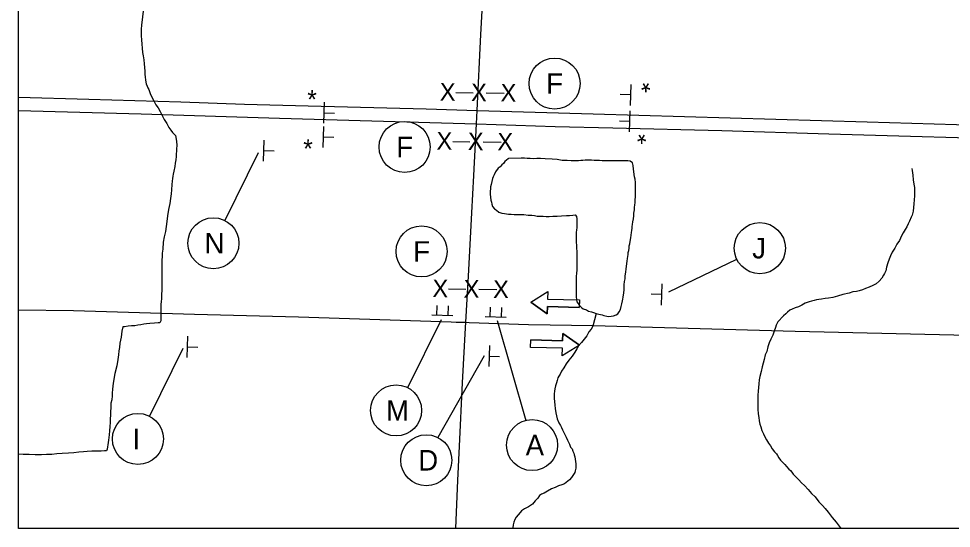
# Model space of a CAD drawing. Extents: x 1633.3 to 1707.6, y 1081.5 to 1106.
# Drawn here: x 1633.31 to 1640.38, y 1086.42 to 1090.29 of the extents above; entities that cross this region are included whole.
import ezdxf

# ---------------------------------------------------------------- set-up
doc = ezdxf.new("R2010")
doc.units = 0
for name, color, linetype in [('GM_X_County_Road', 7, 'Continuous'), ('GM_X_Minor_Lake', 7, 'Continuous'), ('GM_X_Minor_River', 7, 'Continuous'), ('GM_X_State_Route', 7, 'Continuous'), ('GM_X_Township_Road', 7, 'Continuous'), ('SH_Data', 7, 'Continuous'), ('SH_Text', 7, 'Continuous'), ('SN_P_Signs', 7, 'Continuous'), ('SN_X_Public', 7, 'Continuous')]:
    doc.layers.add(name, color=color, linetype=linetype)

msp = doc.modelspace()

# ---------------------------------------------------------------- linework, layer by layer
at = {"layer": 'GM_X_County_Road'}
for points in [[(1636.7895, 1089.5915), (1636.8181, 1090.1691), (1636.886, 1091.3924), (1636.9148, 1091.8728), (1636.9362, 1092.288), (1636.9703, 1092.8778), (1636.974, 1092.925), (1636.9808, 1092.9969), (1636.984, 1093.031)], [(1636.7846, 1089.489), (1636.7895, 1089.5915)], [(1636.7029, 1087.9843), (1636.723, 1088.3341), (1636.7482, 1088.8147), (1636.7628, 1089.0988), (1636.7846, 1089.489)], [(1633.3121, 1088.0796), (1633.7283, 1088.0729), (1634.6468, 1088.0465), (1635.434, 1088.0244), (1636.593, 1087.987), (1636.6307, 1087.986), (1636.7029, 1087.9843)], [(1636.7029, 1087.9843), (1636.7291, 1087.9834), (1637.1782, 1087.9683), (1637.6688, 1087.9589), (1639.2, 1087.9178), (1640.4033, 1087.8897), (1641.5407, 1087.8579), (1642.8312, 1087.8177), (1643.7062, 1087.7937), (1643.8593, 1087.7897)]]:
    msp.add_lwpolyline(points, dxfattribs=at)
at = {"layer": 'GM_X_Minor_Lake'}
for points in [[(1637.0279, 1089.2269), (1637.0241, 1089.2247), (1637, 1089.2034), (1636.9892, 1089.19), (1636.9758, 1089.1794), (1636.9624, 1089.1634), (1636.949, 1089.1527), (1636.9275, 1089.126), (1636.9168, 1089.102), (1636.9114, 1089.0886), (1636.906, 1089.0753), (1636.8952, 1089.0298), (1636.8898, 1089.0111), (1636.8898, 1088.9977), (1636.8871, 1088.979), (1636.887, 1088.9576), (1636.8896, 1088.9335), (1636.8923, 1088.9121), (1636.8976, 1088.896), (1636.9002, 1088.88), (1636.9055, 1088.8639), (1636.9216, 1088.8451), (1636.9349, 1088.8344), (1636.9536, 1088.8209), (1636.975, 1088.8128), (1636.9964, 1088.8101), (1637.0124, 1088.8074), (1637.0258, 1088.8047), (1637.0472, 1088.8046), (1637.0686, 1088.8018), (1637.0927, 1088.8018), (1637.1168, 1088.8017), (1637.1435, 1088.8016), (1637.1756, 1088.7962), (1637.2024, 1088.7961), (1637.2238, 1088.7933), (1637.2452, 1088.7906), (1637.2693, 1088.7905), (1637.2907, 1088.7904), (1637.3121, 1088.7877), (1637.3362, 1088.7876), (1637.3629, 1088.7902), (1637.395, 1088.7901), (1637.4298, 1088.7927), (1637.4673, 1088.7952), (1637.4887, 1088.7952), (1637.5154, 1088.7977), (1637.5315, 1088.8004), (1637.5422, 1088.787), (1637.5448, 1088.7682), (1637.5448, 1088.7522), (1637.5447, 1088.7308), (1637.5447, 1088.7174), (1637.5447, 1088.7013), (1637.542, 1088.6853), (1637.5392, 1088.6666), (1637.5392, 1088.6479), (1637.5392, 1088.6345), (1637.5391, 1088.6184), (1637.5391, 1088.6024), (1637.5391, 1088.589), (1637.5417, 1088.5702), (1637.5416, 1088.5462), (1637.5443, 1088.5221), (1637.5442, 1088.498), (1637.5442, 1088.4793), (1637.5441, 1088.4632), (1637.5441, 1088.4418), (1637.544, 1088.4231), (1637.544, 1088.4044), (1637.5439, 1088.3803), (1637.5412, 1088.3562), (1637.5411, 1088.3321), (1637.5411, 1088.3081), (1637.541, 1088.2893), (1637.541, 1088.2706), (1637.541, 1088.2492), (1637.5409, 1088.2331), (1637.5409, 1088.2171), (1637.5408, 1088.1984), (1637.5408, 1088.1796), (1637.5434, 1088.1555), (1637.546, 1088.1395), (1637.554, 1088.1261), (1637.5647, 1088.1127), (1637.5807, 1088.0966), (1637.5941, 1088.0858), (1637.6182, 1088.0777), (1637.6342, 1088.0696), (1637.6556, 1088.0642), (1637.6716, 1088.0588), (1637.6903, 1088.0507), (1637.7117, 1088.0453), (1637.7358, 1088.0399), (1637.7492, 1088.0345), (1637.7732, 1088.0317), (1637.7866, 1088.029), (1637.8054, 1088.0316), (1637.8241, 1088.0343), (1637.8428, 1088.0396)], [(1637.8428, 1088.0396), (1637.8562, 1088.0475), (1637.867, 1088.0635), (1637.875, 1088.0823), (1637.8804, 1088.1036), (1637.8858, 1088.125), (1637.8912, 1088.1464), (1637.894, 1088.1598), (1637.8967, 1088.1758), (1637.9021, 1088.2079), (1637.9048, 1088.2293), (1637.9049, 1088.248), (1637.9049, 1088.2694), (1637.9076, 1088.2935), (1637.9104, 1088.3149), (1637.9104, 1088.3336), (1637.9131, 1088.3523), (1637.9158, 1088.3657), (1637.9186, 1088.3898), (1637.9267, 1088.4486), (1637.9294, 1088.4673), (1637.9322, 1088.4834), (1637.9349, 1088.4994), (1637.9349, 1088.5128), (1637.9403, 1088.5289), (1637.943, 1088.5476), (1637.943, 1088.5636), (1637.9458, 1088.5797), (1637.9485, 1088.5984), (1637.9539, 1088.6251), (1637.9566, 1088.6465), (1637.9593, 1088.6652), (1637.962, 1088.6813), (1637.9648, 1088.6973), (1637.9648, 1088.7107), (1637.9675, 1088.7267), (1637.9702, 1088.7455), (1637.9756, 1088.7695), (1637.9784, 1088.7909), (1637.9784, 1088.8123), (1637.9811, 1088.8364), (1637.9812, 1088.8578), (1637.9839, 1088.8738), (1637.9866, 1088.8926), (1637.9866, 1088.914), (1637.9894, 1088.9354), (1637.9894, 1088.9568), (1637.9895, 1088.9755), (1637.9895, 1088.9942), (1637.9896, 1089.0129), (1637.9896, 1089.029), (1637.9896, 1089.0451), (1637.987, 1089.0691), (1637.9817, 1089.0879), (1637.9791, 1089.1066), (1637.9764, 1089.128), (1637.9738, 1089.1468), (1637.9712, 1089.1735), (1637.9659, 1089.1949), (1637.9499, 1089.2057), (1637.9311, 1089.2084), (1637.9097, 1089.2085), (1637.8964, 1089.2085), (1637.8803, 1089.2086), (1637.8562, 1089.2087), (1637.8402, 1089.2087), (1637.8268, 1089.2088), (1637.8107, 1089.2088), (1637.7974, 1089.2089), (1637.784, 1089.2089), (1637.7679, 1089.209), (1637.7519, 1089.209), (1637.7358, 1089.2091), (1637.7171, 1089.2118), (1637.6984, 1089.2119), (1637.6769, 1089.2119), (1637.6556, 1089.2147), (1637.6261, 1089.2148), (1637.6074, 1089.2148), (1637.5913, 1089.2122), (1637.5753, 1089.2123), (1637.5565, 1089.2096), (1637.5325, 1089.2097), (1637.503, 1089.2098), (1637.4709, 1089.2126), (1637.4335, 1089.2127), (1637.396, 1089.2182), (1637.3586, 1089.221), (1637.305, 1089.2238), (1637.2703, 1089.2266), (1637.2408, 1089.2267), (1637.2141, 1089.2241), (1637.19, 1089.2269), (1637.1686, 1089.2269), (1637.1472, 1089.2297), (1637.1231, 1089.2297), (1637.0279, 1089.2269)]]:
    msp.add_lwpolyline(points, dxfattribs=at)
at = {"layer": 'GM_X_Minor_River'}
for points in [[(1634.26, 1090.3652), (1634.2436, 1090.2395), (1634.2409, 1090.2074), (1634.2408, 1090.1833), (1634.2408, 1090.1566), (1634.2434, 1090.1272), (1634.246, 1090.0951), (1634.2486, 1090.0629), (1634.2512, 1090.0308), (1634.2565, 1090.0067), (1634.2618, 1089.9746), (1634.2644, 1089.9452), (1634.267, 1089.9184), (1634.2696, 1089.889), (1634.2695, 1089.8676), (1634.2722, 1089.8435), (1634.2748, 1089.8247), (1634.2774, 1089.806), (1634.2801, 1089.7926), (1634.2854, 1089.7765), (1634.2907, 1089.7632), (1634.2987, 1089.7497), (1634.3094, 1089.7203), (1634.3227, 1089.6935), (1634.336, 1089.664), (1634.352, 1089.6345), (1634.3706, 1089.6104), (1634.384, 1089.5836), (1634.3999, 1089.5541), (1634.4159, 1089.522), (1634.4346, 1089.4925), (1634.4506, 1089.463), (1634.4666, 1089.4415), (1634.4799, 1089.4254), (1634.5013, 1089.4013), (1634.5092, 1089.3585), (1634.5118, 1089.3263), (1634.5091, 1089.2996)], [(1634.5091, 1089.2996), (1634.509, 1089.2809), (1634.5063, 1089.2648), (1634.5062, 1089.2434), (1634.5035, 1089.2167), (1634.4981, 1089.1926), (1634.4954, 1089.1659), (1634.4899, 1089.1311), (1634.4845, 1089.1071), (1634.4818, 1089.0937), (1634.4791, 1089.075), (1634.4764, 1089.0562), (1634.4736, 1089.0295), (1634.4709, 1088.9894), (1634.4682, 1088.96), (1634.4627, 1088.9225), (1634.4573, 1088.8851), (1634.4491, 1088.8396), (1634.441, 1088.7915), (1634.4356, 1088.7487), (1634.4301, 1088.7113), (1634.4247, 1088.6738), (1634.4166, 1088.6337), (1634.4084, 1088.5909), (1634.4056, 1088.5401), (1634.4002, 1088.508), (1634.4002, 1088.4813), (1634.3974, 1088.4572), (1634.3974, 1088.4304), (1634.3973, 1088.409), (1634.3973, 1088.3876), (1634.3972, 1088.3635), (1634.3971, 1088.3315), (1634.3971, 1088.2993), (1634.397, 1088.2646), (1634.3969, 1088.2325), (1634.3941, 1088.1897), (1634.3941, 1088.1629), (1634.394, 1088.1415), (1634.3913, 1088.1201), (1634.3913, 1088.1014), (1634.3912, 1088.0746), (1634.3911, 1088.0532), (1634.3911, 1088.0318), (1634.3911, 1088.0131), (1634.391, 1087.9944), (1634.383, 1087.981), (1634.3696, 1087.9811), (1634.3428, 1087.9785), (1634.308, 1087.9759), (1634.2813, 1087.9733), (1634.2625, 1087.9707), (1634.2384, 1087.9654), (1634.217, 1087.9628), (1634.1929, 1087.9575), (1634.1688, 1087.9576), (1634.1421, 1087.955), (1634.1153, 1087.9498), (1634.1019, 1087.9498), (1634.0938, 1087.9177), (1634.0884, 1087.8723), (1634.0802, 1087.8268), (1634.0775, 1087.792), (1634.0721, 1087.768), (1634.0693, 1087.7385), (1634.0639, 1087.7011), (1634.0558, 1087.653), (1634.0423, 1087.5968), (1634.0287, 1087.522), (1634.0232, 1087.4765), (1634.0205, 1087.4471), (1634.0205, 1087.4257), (1634.0177, 1087.3962), (1634.0123, 1087.3695), (1634.0122, 1087.3374), (1634.0095, 1087.3053), (1634.0094, 1087.2785), (1634.0067, 1087.2518), (1634.0066, 1087.2251), (1634.0039, 1087.1929), (1634.0011, 1087.1609), (1633.9984, 1087.1314), (1633.9957, 1087.11), (1633.9929, 1087.0886), (1633.9902, 1087.0726), (1633.9821, 1087.0218), (1633.9794, 1087.0084), (1633.9633, 1087.0085), (1633.9366, 1087.0059), (1633.9044, 1087.006), (1633.867, 1087.0061), (1633.8322, 1087.0035), (1633.8028, 1087.001), (1633.768, 1086.9984), (1633.7305, 1086.9932), (1633.6903, 1086.9906), (1633.6422, 1086.9881), (1633.602, 1086.9855), (1633.5646, 1086.9803), (1633.5244, 1086.9804), (1633.4843, 1086.9779)], [(1640.085, 1089.1507), (1640.0876, 1089.1347), (1640.0929, 1089.0999), (1640.0955, 1089.0651), (1640.1008, 1089.033), (1640.1061, 1089.0062), (1640.106, 1088.9768), (1640.1059, 1088.9447), (1640.1032, 1088.9126), (1640.1004, 1088.8831), (1640.0977, 1088.8564), (1640.0949, 1088.827), (1640.0868, 1088.7976), (1640.0815, 1088.7815), (1640.068, 1088.7521), (1640.0573, 1088.7308), (1640.0465, 1088.7094), (1640.0358, 1088.688), (1640.0196, 1088.664), (1640.0062, 1088.64), (1639.9928, 1088.6052), (1639.9713, 1088.5759), (1639.9552, 1088.5465), (1639.9364, 1088.5171), (1639.9229, 1088.4877), (1639.9122, 1088.4637), (1639.9041, 1088.4343), (1639.8933, 1088.4022), (1639.8879, 1088.3755), (1639.8771, 1088.3541), (1639.8717, 1088.3408), (1639.8583, 1088.3194), (1639.8369, 1088.2954), (1639.8154, 1088.2767), (1639.7886, 1088.2634), (1639.7618, 1088.2501), (1639.735, 1088.2395), (1639.711, 1088.2316), (1639.6868, 1088.2236), (1639.6654, 1088.2183), (1639.6387, 1088.2158), (1639.6092, 1088.2051), (1639.561, 1088.1946), (1639.5209, 1088.1813), (1639.486, 1088.1734), (1639.4539, 1088.1682), (1639.4272, 1088.1656), (1639.4004, 1088.1603), (1639.379, 1088.1577), (1639.3629, 1088.1551), (1639.3442, 1088.1498), (1639.3254, 1088.1445), (1639.3067, 1088.1392), (1639.2772, 1088.1286), (1639.2504, 1088.1153), (1639.2263, 1088.102), (1639.1996, 1088.0941), (1639.1781, 1088.0835), (1639.1594, 1088.0755), (1639.1433, 1088.0622), (1639.1299, 1088.0488), (1639.1111, 1088.0328), (1639.0682, 1087.9875), (1639.0575, 1087.9634), (1639.0521, 1087.9447), (1639.0413, 1087.918), (1639.0305, 1087.8859), (1639.0171, 1087.8566), (1639.0036, 1087.8272), (1638.9928, 1087.7978), (1638.9847, 1087.763), (1638.974, 1087.7363), (1638.9659, 1087.7015), (1638.9497, 1087.6454), (1638.9416, 1087.6107), (1638.9335, 1087.5732), (1638.928, 1087.5465), (1638.9253, 1087.5171), (1638.9226, 1087.4903), (1638.9198, 1087.4609), (1638.9171, 1087.4315), (1638.917, 1087.394), (1638.9169, 1087.3592), (1638.9168, 1087.3245), (1638.9194, 1087.2897), (1638.9247, 1087.2629), (1638.9274, 1087.2361), (1638.9326, 1087.212), (1638.9406, 1087.1906), (1638.9486, 1087.1638), (1638.9592, 1087.137), (1638.9699, 1087.1156), (1638.9832, 1087.0915), (1638.9992, 1087.0673), (1639.0125, 1087.0459), (1639.0259, 1087.0245), (1639.0445, 1087.0003), (1639.0579, 1086.9869), (1639.0659, 1086.9735), (1639.0765, 1086.9547), (1639.0899, 1086.9386)], [(1637.6903, 1088.0507), (1637.666, 1087.9545), (1637.6526, 1087.9331), (1637.6365, 1087.9118), (1637.6204, 1087.8824), (1637.6016, 1087.8557), (1637.5801, 1087.8317), (1637.5587, 1087.805), (1637.5452, 1087.7837), (1637.5291, 1087.7569), (1637.5103, 1087.7276), (1637.4835, 1087.6956), (1637.4647, 1087.6689), (1637.4459, 1087.6395), (1637.4298, 1087.6128), (1637.419, 1087.5914), (1637.4083, 1087.5754), (1637.4002, 1087.5621), (1637.3948, 1087.5433), (1637.3895, 1087.5246), (1637.384, 1087.5032), (1637.3786, 1087.4792), (1637.3759, 1087.4605), (1637.3732, 1087.4417), (1637.3732, 1087.4257), (1637.3731, 1087.407), (1637.3758, 1087.3829), (1637.3784, 1087.3561), (1637.381, 1087.3293), (1637.3863, 1087.2972), (1637.3969, 1087.2517), (1637.4075, 1087.2223), (1637.4208, 1087.2008), (1637.4288, 1087.1847), (1637.4368, 1087.1686), (1637.4448, 1087.1526), (1637.4528, 1087.1338), (1637.4634, 1087.1124), (1637.4741, 1087.0909), (1637.4821, 1087.0749), (1637.4901, 1087.0588), (1637.498, 1087.0373), (1637.5087, 1087.0239), (1637.514, 1087.0052), (1637.522, 1086.9918), (1637.5247, 1086.9784), (1637.53, 1086.9623), (1637.5379, 1086.9115), (1637.5379, 1086.8954), (1637.5378, 1086.8767), (1637.5324, 1086.858), (1637.5297, 1086.8446), (1637.5136, 1086.8206), (1637.5055, 1086.8072), (1637.4894, 1086.7886), (1637.476, 1086.7779), (1637.4519, 1086.7593), (1637.4305, 1086.7513), (1637.4064, 1086.7433), (1637.3796, 1086.7301), (1637.3528, 1086.7194), (1637.3234, 1086.7035), (1637.2966, 1086.6875), (1637.2778, 1086.6795), (1637.2617, 1086.6689), (1637.2483, 1086.6502), (1637.2295, 1086.6289), (1637.2081, 1086.6049), (1637.1786, 1086.5835), (1637.1625, 1086.5756), (1637.1491, 1086.5676), (1637.125, 1086.5543), (1637.1143, 1086.5409), (1637.1008, 1086.5223), (1637.0848, 1086.5063), (1637.074, 1086.4876), (1637.0659, 1086.4689), (1637.0632, 1086.4475), (1637.0605, 1086.4234), (1637.0605, 1086.4207)], [(1633.4843, 1086.9779), (1633.4361, 1086.9781), (1633.3906, 1086.9809), (1633.3452, 1086.981), (1633.3121, 1086.9831)], [(1639.0899, 1086.9386), (1639.1032, 1086.9252), (1639.1219, 1086.9064), (1639.1353, 1086.8903), (1639.1513, 1086.8689), (1639.1646, 1086.8608), (1639.1753, 1086.8474), (1639.186, 1086.8313), (1639.2287, 1086.7884), (1639.2474, 1086.7669), (1639.2714, 1086.7454), (1639.2981, 1086.7159), (1639.3248, 1086.6864), (1639.3515, 1086.6596), (1639.3808, 1086.622), (1639.4075, 1086.5952), (1639.4289, 1086.571), (1639.4502, 1086.5442), (1639.4662, 1086.5227), (1639.4822, 1086.504), (1639.4956, 1086.4852), (1639.5116, 1086.4664), (1639.5276, 1086.4476), (1639.5409, 1086.4262), (1639.5457, 1086.4207)]]:
    msp.add_lwpolyline(points, dxfattribs=at)
at = {"layer": 'GM_X_State_Route'}
for points in [[(1633.3121, 1089.6917), (1633.8444, 1089.6764), (1634.5421, 1089.656), (1635.0244, 1089.6397), (1635.5067, 1089.6277), (1636.4013, 1089.603), (1636.7895, 1089.5915), (1637.6692, 1089.5652), (1639.746, 1089.5046), (1640.4237, 1089.486), (1640.9483, 1089.4695), (1641.5823, 1089.4514), (1642.6316, 1089.4208), (1643.4405, 1089.3971), (1643.9071, 1089.384), (1643.9651, 1089.3826), (1644.8177, 1089.3571), (1645.2987, 1089.3441), (1645.9544, 1089.3239), (1646.3915, 1089.3102), (1647.5918, 1089.2715), (1647.7355, 1089.2693), (1648.0121, 1089.264)], [(1633.3121, 1089.5922), (1634.2415, 1089.565), (1635.2906, 1089.5338), (1635.99, 1089.5137), (1636.7846, 1089.489), (1637.3802, 1089.4708), (1637.8182, 1089.4595), (1638.6457, 1089.4389), (1639.4549, 1089.4149), (1641.0515, 1089.3682), (1641.6858, 1089.3496), (1642.145, 1089.338), (1643.2823, 1089.3034), (1643.9044, 1089.2854), (1644.5726, 1089.2656), (1645.9723, 1089.2243), (1647.0002, 1089.1934), (1647.8935, 1089.1689), (1648.0121, 1089.1646)]]:
    msp.add_lwpolyline(points, dxfattribs=at)
at = {"layer": 'GM_X_Township_Road'}
msp.add_lwpolyline([(1636.628, 1086.4207), (1636.6329, 1086.5425), (1636.6436, 1086.7828), (1636.655, 1087.0451), (1636.6786, 1087.5259), (1636.7003, 1087.941), (1636.7029, 1087.9843)], dxfattribs=at)
at = {"layer": 'SH_Data'}
msp.add_lwpolyline([(1633.3121, 1106.0207), (1648.0121, 1106.0207), (1648.0121, 1086.4207), (1633.3121, 1086.4207)], close=True, dxfattribs=at)
at = {"layer": 'SH_Text'}
for p, q in [((1635.1295, 1089.2708), (1634.8764, 1088.7569)), ((1638.2414, 1088.2151), (1638.7572, 1088.4644)), ((1637.1949, 1088.1366), (1637.3248, 1088.2177)), ((1637.3248, 1088.2177), (1637.3231, 1088.1608)), ((1637.1949, 1088.1366), (1637.3199, 1088.0482)), ((1637.3199, 1088.0482), (1637.3215, 1088.1028)), ((1637.3215, 1088.1028), (1637.5634, 1088.0959)), ((1637.3231, 1088.1608), (1637.5651, 1088.1539)), ((1637.5651, 1088.1539), (1637.5634, 1088.0959)), ((1636.5152, 1088.0018), (1636.262, 1087.4879)), ((1636.9401, 1087.9983), (1637.1579, 1087.2402)), ((1637.4389, 1087.8992), (1637.4373, 1087.8447)), ((1637.5639, 1087.8108), (1637.4389, 1087.8992)), ((1637.1937, 1087.7936), (1637.1954, 1087.8515)), ((1637.4373, 1087.8447), (1637.1954, 1087.8515)), ((1637.5639, 1087.8108), (1637.4341, 1087.7297)), ((1634.5572, 1087.7854), (1634.304, 1087.2715)), ((1637.4357, 1087.7867), (1637.1937, 1087.7936)), ((1637.4341, 1087.7297), (1637.4357, 1087.7867)), ((1636.8418, 1087.7308), (1636.491, 1087.1101))]:
    msp.add_line(p, q, dxfattribs=at)
for points in [[(1637.5634, 1088.0959), (1637.3215, 1088.1028), (1637.3199, 1088.0482), (1637.1949, 1088.1366), (1637.3247, 1088.2177), (1637.3231, 1088.1608), (1637.5651, 1088.1539)], [(1637.1954, 1087.8515), (1637.4373, 1087.8447), (1637.4389, 1087.8992), (1637.5639, 1087.8108), (1637.4341, 1087.7297), (1637.4357, 1087.7867), (1637.1937, 1087.7936)]]:
    msp.add_lwpolyline(points, close=True, dxfattribs=at)
msp.add_lwpolyline([(1636.7029, 1087.9843), (1636.7291, 1087.9834), (1637.1782, 1087.9683), (1637.6688, 1087.9589), (1639.2, 1087.9178), (1640.4033, 1087.8897), (1641.5407, 1087.8579), (1642.8312, 1087.8177), (1643.7062, 1087.7937), (1643.8593, 1087.7897)], dxfattribs=at)
for centre in [(1637.3758, 1089.7959), (1636.2392, 1089.3145), (1634.7888, 1088.5842), (1638.9325, 1088.5467), (1636.3673, 1088.5217), (1636.1744, 1087.3153), (1634.2164, 1087.0989), (1637.2055, 1087.0525), (1636.4034, 1086.9375)]:
    msp.add_circle(centre, 0.1936, dxfattribs=at)
at = {"layer": 'SN_P_Signs'}
for p, q in [((1636.6279, 1089.7279), (1636.7581, 1089.7262)), ((1636.8582, 1089.7249), (1636.995, 1089.7231)), ((1635.171, 1089.3673), (1635.1663, 1089.2074)), ((1636.6034, 1089.3561), (1636.7335, 1089.3544)), ((1636.8337, 1089.3531), (1636.9705, 1089.3513)), ((1635.1686, 1089.2874), (1635.2486, 1089.285)), ((1636.5719, 1088.2373), (1636.7021, 1088.2356)), ((1636.8022, 1088.2343), (1636.939, 1088.2325)), ((1638.1866, 1088.1149), (1638.1913, 1088.2749)), ((1638.1889, 1088.1949), (1638.109, 1088.1973)), ((1636.4845, 1088.0364), (1636.4869, 1088.1117)), ((1636.5687, 1088.0337), (1636.5712, 1088.109)), ((1636.8881, 1088.0241), (1636.8906, 1088.0994)), ((1636.9724, 1088.0214), (1636.9749, 1088.0967)), ((1636.6056, 1088.0325), (1636.446, 1088.0377)), ((1637.0093, 1088.0202), (1636.8497, 1088.0254)), ((1634.593, 1087.878), (1634.5883, 1087.718)), ((1636.8816, 1087.8082), (1636.8769, 1087.6483)), ((1634.5906, 1087.798), (1634.6706, 1087.7956)), ((1636.8792, 1087.7282), (1636.9592, 1087.7258))]:
    msp.add_line(p, q, dxfattribs=at)
at = {"layer": 'SN_X_Public'}
for p, q in [((1637.9514, 1089.6295), (1637.956, 1089.7894)), ((1635.6287, 1089.6542), (1635.624, 1089.4942)), ((1637.9537, 1089.7095), (1637.8737, 1089.7118)), ((1637.9455, 1089.4286), (1637.9502, 1089.5885)), ((1635.6264, 1089.5742), (1635.7063, 1089.5719)), ((1637.9478, 1089.5085), (1637.8679, 1089.5109)), ((1635.6233, 1089.4705), (1635.6187, 1089.3105)), ((1635.621, 1089.3905), (1635.701, 1089.3882))]:
    msp.add_line(p, q, dxfattribs=at)

# ---------------------------------------------------------------- texts
at = {"layer": 'SH_Text'}
for s, height, p in [('F', 0.156, (1637.3125, 1089.7179)), ('*', 0.14, (1635.5008, 1089.6057)), ('*', 0.14, (1635.4702, 1089.232)), ('F', 0.156, (1636.176, 1089.2365)), ('N', 0.156, (1634.7219, 1088.5062)), ('F', 0.156, (1636.3041, 1088.4437)), ('J', 0.156, (1638.8747, 1088.4687)), ('M', 0.156, (1636.0983, 1087.2373)), ('I', 0.156, (1634.1759, 1087.0209)), ('A', 0.156, (1637.157, 1086.9745)), ('D', 0.156, (1636.3426, 1086.8595))]:
    msp.add_text(s, height=height, dxfattribs=at).set_placement(p)
for p in [(1638.1045, 1089.8679), (1638.0734, 1089.4771)]:
    msp.add_text('*', height=0.14, rotation=180, dxfattribs=at).set_placement(p)
at = {"layer": 'SN_P_Signs'}
for p in [(1636.5051, 1089.6659), (1636.742, 1089.6629), (1636.9656, 1089.6599), (1636.4805, 1089.2942), (1636.7175, 1089.2911), (1636.9411, 1089.2881), (1636.4491, 1088.1753), (1636.686, 1088.1722), (1636.9096, 1088.1693)]:
    msp.add_text('X', height=0.1333, rotation=359.25135, dxfattribs=at).set_placement(p)

doc.saveas('drawing.dxf')
